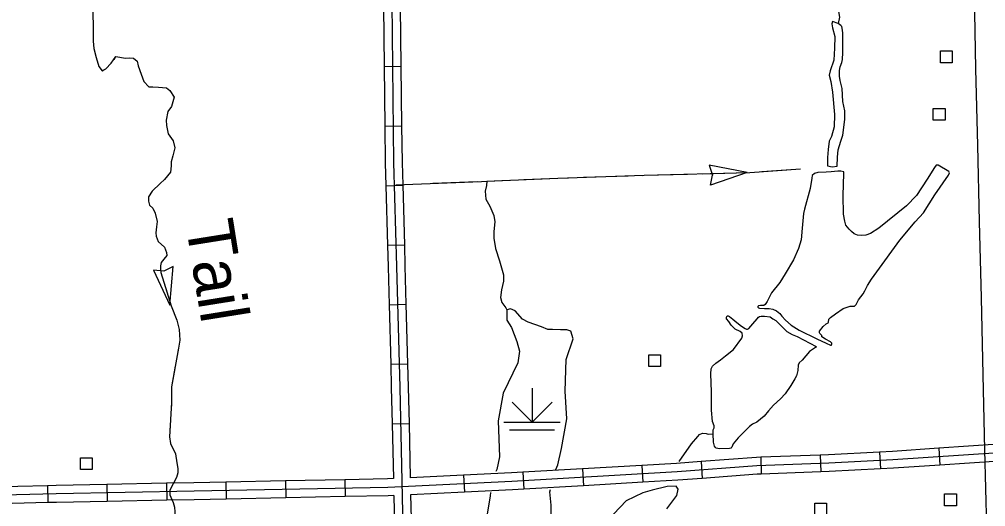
# Model space of a CAD drawing. Extents: x 1084508 to 1142749, y 1057638 to 1093403.
# Drawn here: x 1106590 to 1109281, y 1082416 to 1083772 of the extents above; entities that cross this region are included whole.
import ezdxf

# ---------------------------------------------------------------- set-up
doc = ezdxf.new("R2010")
doc.units = 0
for name, color, linetype in [('Level 10', 7, 'Continuous'), ('Level 32', 7, 'Continuous'), ('Level 35', 7, 'Continuous'), ('Level 43', 7, 'Continuous'), ('Level 44', 7, 'Continuous'), ('Level 47', 7, 'Continuous'), ('Level 56', 7, 'Continuous')]:
    doc.layers.add(name, color=color, linetype=linetype)

msp = doc.modelspace()

# ---------------------------------------------------------------- linework, layer by layer
at = {"layer": 'Level 10'}
msp.add_lwpolyline([(1109217.8, 1085327.2), (1109222.4, 1085115.2), (1109226.6, 1084906.4), (1109230, 1084691.2), (1109234.9, 1084482.4), (1109240.1, 1084267.5), (1109243.8, 1084054.2), (1109248.7, 1083844.6), (1109252.9, 1083634.1), (1109258.1, 1083420.9), (1109262.4, 1083209.7), (1109268.8, 1082997.4), (1109273.1, 1082783.1), (1109277.7, 1082574), (1109283.5, 1082358.9)], dxfattribs=at)
at = {"layer": 'Level 32'}
for p, q in [((1107605.5, 1083641), (1107652.6, 1083641.5)), ((1107607.4, 1083475.3), (1107654.5, 1083475.8)), ((1107610.4, 1083309.2), (1107657.5, 1083310.5)), ((1107615, 1083143.5), (1107662.1, 1083144.9)), ((1107619.6, 1082977.9), (1107666.6, 1082979.2)), ((1107624, 1082812.2), (1107671.1, 1082813.5)), ((1107628, 1082646.6), (1107675.1, 1082647.7)), ((1109150.2, 1082578.3), (1109153.4, 1082531.4)), ((1108654.4, 1082553.5), (1108656.1, 1082506.5)), ((1108820, 1082559.6), (1108821.7, 1082512.5)), ((1108985.2, 1082567.8), (1108987.6, 1082520.8)), ((1108323.3, 1082530.7), (1108326, 1082483.7)), ((1108488.2, 1082541.5), (1108491.8, 1082494.5)), ((1107827.1, 1082503.3), (1107829.3, 1082456.3)), ((1107992.3, 1082511.6), (1107995.1, 1082464.6)), ((1108157.8, 1082521.2), (1108160.5, 1082474.2)), ((1106667.9, 1082474.1), (1106669.1, 1082427)), ((1106833.7, 1082477.5), (1106834.7, 1082430.5)), ((1106999.4, 1082480.9), (1107000.4, 1082433.8)), ((1107165.1, 1082484.2), (1107166.1, 1082437.1)), ((1107330.8, 1082487.5), (1107331.8, 1082440.4)), ((1107496.5, 1082490.8), (1107497.5, 1082443.7))]:
    msp.add_line(p, q, dxfattribs=at)
for points in [[(1107601.5, 1085146.9), (1107603.3, 1084972.6), (1107614.1, 1084619.6), (1107615.9, 1084430.9), (1107624.9, 1083998.3), (1107632.1, 1083373.5), (1107640.3, 1083084.5), (1107649.3, 1082747.7), (1107660.1, 1082270)], [(1107603.6, 1083806.7), (1107605.5, 1083641)], [(1107650.7, 1083807.3), (1107652.6, 1083641.5)], [(1107605.5, 1083641), (1107607.4, 1083475.3)], [(1107652.6, 1083641.5), (1107654.5, 1083475.8)], [(1107607.4, 1083475.3), (1107608.6, 1083373), (1107610.4, 1083309.2)], [(1107654.5, 1083475.8), (1107655.7, 1083373.9), (1107657.5, 1083310.5)], [(1107610.4, 1083309.2), (1107615, 1083143.5)], [(1107657.5, 1083310.5), (1107662.1, 1083144.9)], [(1107615, 1083143.5), (1107616.7, 1083083.8), (1107619.6, 1082977.9)], [(1107662.1, 1083144.9), (1107663.8, 1083085.1), (1107666.6, 1082979.2)], [(1107619.6, 1082977.9), (1107624, 1082812.2)], [(1107666.6, 1082979.2), (1107671.1, 1082813.5)], [(1107624, 1082812.2), (1107625.7, 1082747.1), (1107628, 1082646.6)], [(1107671.1, 1082813.5), (1107672.8, 1082748.3), (1107675.1, 1082647.7)], [(1107628, 1082646.6), (1107631.5, 1082493.9)], [(1107675.1, 1082647.7), (1107678.5, 1082496.2)], [(1109150.2, 1082578.3), (1109021.3, 1082569.7), (1108985.2, 1082567.8)], [(1109315.6, 1082589.4), (1109150.2, 1082578.3)], [(1109317.2, 1082565.9), (1109022.7, 1082546.2), (1108844.3, 1082536.9), (1108643.6, 1082529.6), (1108421.8, 1082512.9), (1107961.6, 1082486.3), (1107616.3, 1082469.6), (1107076.7, 1082458.9), (1106692.8, 1082451.1), (1106360.3, 1082443)], [(1108654.4, 1082553.5), (1108642.3, 1082553.1), (1108488.2, 1082541.5)], [(1108820, 1082559.6), (1108654.4, 1082553.5)], [(1108985.2, 1082567.8), (1108843.3, 1082560.4), (1108820, 1082559.6)], [(1108323.3, 1082530.7), (1108157.8, 1082521.2)], [(1108488.2, 1082541.5), (1108420.3, 1082536.3), (1108323.3, 1082530.7)], [(1109153.4, 1082531.4), (1109024.1, 1082522.7), (1108987.6, 1082520.8)], [(1109318.7, 1082542.4), (1109153.4, 1082531.4)], [(1107827.1, 1082503.3), (1107678.5, 1082496.2)], [(1107992.3, 1082511.6), (1107960.3, 1082509.8), (1107827.1, 1082503.3)], [(1108157.8, 1082521.2), (1107992.3, 1082511.6)], [(1108656.1, 1082506.5), (1108644.9, 1082506.1), (1108491.8, 1082494.5)], [(1108821.7, 1082512.5), (1108656.1, 1082506.5)], [(1108987.6, 1082520.8), (1108845.4, 1082513.4), (1108821.7, 1082512.5)], [(1106667.9, 1082474.1), (1106502.3, 1082470)], [(1106833.7, 1082477.5), (1106692.2, 1082474.7), (1106667.9, 1082474.1)], [(1106999.4, 1082480.9), (1106833.7, 1082477.5)], [(1107165.1, 1082484.2), (1107076.2, 1082482.4), (1106999.4, 1082480.9)], [(1107330.8, 1082487.5), (1107165.1, 1082484.2)], [(1107496.5, 1082490.8), (1107330.8, 1082487.5)], [(1107631.5, 1082493.9), (1107615.5, 1082493.1), (1107496.5, 1082490.8)], [(1108160.5, 1082474.2), (1107995.1, 1082464.6)], [(1108326, 1082483.7), (1108160.5, 1082474.2)], [(1108491.8, 1082494.5), (1108423.4, 1082489.4), (1108326, 1082483.7)], [(1107497.5, 1082443.7), (1107331.8, 1082440.4)], [(1107632.6, 1082446.8), (1107617.1, 1082446.1), (1107497.5, 1082443.7)], [(1107632.6, 1082446.8), (1107635.5, 1082315.3)], [(1107829.3, 1082456.3), (1107679.6, 1082449.1)], [(1107679.6, 1082449.1), (1107682.6, 1082316.3)], [(1107995.1, 1082464.6), (1107962.8, 1082462.7), (1107829.3, 1082456.3)], [(1106669.1, 1082427), (1106503.4, 1082423)], [(1106834.7, 1082430.5), (1106693.3, 1082427.6), (1106669.1, 1082427)], [(1107000.4, 1082433.8), (1106834.7, 1082430.5)], [(1107166.1, 1082437.1), (1107077.1, 1082435.3), (1107000.4, 1082433.8)], [(1107331.8, 1082440.4), (1107166.1, 1082437.1)]]:
    msp.add_lwpolyline(points, dxfattribs=at)
at = {"layer": 'Level 35'}
for points in [[(1108870.3, 1083760.9), (1108854, 1083766.3), (1108852.4, 1083760.1), (1108854.8, 1083748.4), (1108861, 1083724.3), (1108860.2, 1083691.6), (1108857.9, 1083658.9), (1108847.8, 1083629.3), (1108845.4, 1083616.8), (1108849.3, 1083598.9), (1108854.8, 1083569.3), (1108860.2, 1083507.8), (1108858.6, 1083473.3), (1108851.6, 1083446.1), (1108845.4, 1083432.9), (1108842.3, 1083410.3), (1108840.4, 1083388)], [(1108840.4, 1083388), (1108840.1, 1083364.7), (1108853.4, 1083361.3), (1108867.2, 1083363.2), (1108868.3, 1083388.5), (1108869.7, 1083409.3), (1108877.1, 1083433.1), (1108883.4, 1083449.8), (1108885.3, 1083463.4), (1108888.4, 1083494.2), (1108888.4, 1083517.3), (1108883.3, 1083543.3), (1108881.4, 1083579.9), (1108876, 1083601.7), (1108873.6, 1083614.2), (1108873.6, 1083622.4), (1108873.6, 1083630.2), (1108875.6, 1083640.3), (1108880.6, 1083652.3), (1108881.8, 1083660.9), (1108883, 1083679.6), (1108883, 1083733.8), (1108881.8, 1083742.4), (1108880.6, 1083752.5), (1108877.1, 1083755.6), (1108870.3, 1083760.9)], [(1106859, 1083668.4), (1106885.4, 1083664.4), (1106896.4, 1083665.3), (1106907.3, 1083664.4), (1106917.9, 1083656.1), (1106920.5, 1083643.3), (1106929.3, 1083619.6), (1106936.3, 1083599.4), (1106950, 1083584.8), (1106961.8, 1083584), (1106977.6, 1083583.5), (1106999.6, 1083581.8), (1107008.8, 1083574.3), (1107021.1, 1083555.4), (1107013.7, 1083529.5), (1107003.6, 1083515.4), (1106998.3, 1083492.1), (1107000.1, 1083476.7), (1107004.4, 1083453.8), (1107018.5, 1083434.5), (1107023.3, 1083414.3), (1107017.6, 1083392.3), (1107012.4, 1083375.2), (1107012.4, 1083364.6), (1107011, 1083346.9), (1106994.3, 1083326.7), (1106982, 1083315.7), (1106959.6, 1083294.2), (1106949.1, 1083278.4), (1106949.1, 1083266.5), (1106952.2, 1083255.5), (1106961.8, 1083246.7), (1106968.4, 1083233.1), (1106973.7, 1083209.8), (1106971.5, 1083194.4), (1106970.2, 1083178.1), (1106971, 1083168.9), (1106976.3, 1083153.5), (1106993.9, 1083137.7), (1107000, 1083123.2), (1107000.9, 1083114.7), (1106992.6, 1083105), (1106984.7, 1083095.8), (1106983.3, 1083086.1), (1106983.3, 1083078.7), (1106983.9, 1083067.3)], [(1108849.2, 1082942.3), (1108863, 1082952.4), (1108884, 1082967.6), (1108903.1, 1082973.8), (1108915.5, 1082974.2), (1108920.2, 1082978.9), (1108927.2, 1082991.7), (1108940, 1083008.5), (1108944.3, 1083016.2), (1108951.7, 1083031), (1108963, 1083048.9), (1108978.2, 1083069.6), (1109041.6, 1083157.2), (1109084.4, 1083208.2), (1109108.1, 1083233.9), (1109139.6, 1083283.7), (1109177, 1083338.5), (1109180.1, 1083345.5), (1109178.6, 1083349), (1109148.6, 1083366.5), (1109143.5, 1083366.5), (1109138.5, 1083360.3), (1109117.9, 1083327.2), (1109087.9, 1083282), (1109060.7, 1083253.6), (1108983.6, 1083190.6), (1108960.3, 1083176.2), (1108947, 1083171.5), (1108934.2, 1083170.7), (1108923.7, 1083171.5), (1108915.1, 1083175), (1108907.4, 1083181.6), (1108900.4, 1083188.6), (1108891.4, 1083199.1), (1108889.1, 1083210.4), (1108884.8, 1083229.9), (1108883.6, 1083282), (1108886.3, 1083342.8), (1108886, 1083347.4), (1108877.4, 1083349.4), (1108869.2, 1083349.4), (1108850.9, 1083348.2), (1108836.5, 1083347.1), (1108813.6, 1083345.9), (1108803.9, 1083343.2), (1108797.6, 1083337.3), (1108796.5, 1083330.3), (1108791.8, 1083301.5), (1108776.2, 1083243.9), (1108773.5, 1083231.4), (1108770, 1083191), (1108766.9, 1083159), (1108759.5, 1083134.5), (1108745.5, 1083103), (1108722.9, 1083063.9)], [(1107891.6, 1083322.2), (1107890.6, 1083309.4), (1107887.5, 1083293.9), (1107889, 1083271.3), (1107899.8, 1083252.3), (1107911.1, 1083226.6), (1107914.2, 1083208.6), (1107911.1, 1083181.3), (1107911.6, 1083163.2), (1107915.7, 1083134.4), (1107927, 1083100), (1107937.8, 1083061.4), (1107937.8, 1083043.4), (1107932.7, 1083019.2), (1107929.6, 1082998.1), (1107933.2, 1082983.7), (1107945, 1082969.3), (1107947.5, 1082963.3)], [(1108722.9, 1083063.9), (1108707.3, 1083039.5), (1108684.6, 1083011.1), (1108672.1, 1082986.6), (1108666.7, 1082978.4), (1108662.8, 1082976.1), (1108653.5, 1082975.3), (1108648, 1082974.5), (1108646.8, 1082973), (1108646.8, 1082971), (1108648, 1082969.5), (1108651.1, 1082968.3), (1108664.7, 1082967.5), (1108678.4, 1082967.5), (1108688.1, 1082965.6), (1108698.6, 1082960.5), (1108707.5, 1082953.5), (1108713.4, 1082946.5), (1108723.5, 1082934.9)], [(1108524.9, 1082640.4), (1108520.6, 1082652.7), (1108517.7, 1082684.1), (1108517.5, 1082735.5), (1108515.7, 1082785.7), (1108516.2, 1082799.6), (1108520.6, 1082806.5), (1108529.3, 1082815), (1108542.7, 1082824.3), (1108556, 1082835.8), (1108578.6, 1082853.3), (1108602.3, 1082885), (1108604.1, 1082891.1), (1108602.6, 1082899.1), (1108597.4, 1082903.7), (1108583.5, 1082909.7), (1108572.2, 1082920.8), (1108565.5, 1082931.6), (1108559.4, 1082939), (1108559.4, 1082943.7), (1108561.2, 1082947), (1108564, 1082947), (1108567.3, 1082945.2), (1108576.6, 1082938), (1108587.9, 1082928.2), (1108600.5, 1082918.2), (1108611.3, 1082911.3), (1108614.6, 1082910.2), (1108617.7, 1082910.2), (1108621.8, 1082912), (1108627.2, 1082918.2), (1108632.6, 1082924.9), (1108644.7, 1082938.8), (1108648.3, 1082943.4), (1108651.1, 1082944.7), (1108656, 1082946.2), (1108664.8, 1082946.2), (1108680.7, 1082943.9), (1108688.1, 1082939), (1108696.1, 1082934.4), (1108712.8, 1082917.2), (1108727.2, 1082903.3), (1108742.1, 1082895), (1108756.3, 1082889.8), (1108808.4, 1082861.3), (1108807.1, 1082858.5), (1108801.5, 1082855.6), (1108790.4, 1082847.6), (1108779.9, 1082835.3), (1108769.6, 1082823.5), (1108761.1, 1082815.8), (1108758.6, 1082809.3), (1108757.5, 1082795.2), (1108753.7, 1082780.3), (1108749.8, 1082771.5), (1108738.5, 1082753.5), (1108722.8, 1082729.9), (1108709.7, 1082716), (1108690.2, 1082698.5), (1108676.1, 1082682.6), (1108664, 1082667.4), (1108643.2, 1082651.4), (1108631.8, 1082645), (1108623.1, 1082639.4), (1108615.7, 1082631.6), (1108600, 1082615.7), (1108592, 1082607.7), (1108578.1, 1082590.5), (1108574, 1082581.7), (1108572.2, 1082579.9), (1108571.7, 1082578.7), (1108567.6, 1082577.6), (1108540.1, 1082577.1), (1108530.6, 1082578.4), (1108527.5, 1082581), (1108525.7, 1082584.3), (1108523.1, 1082594.9), (1108521.8, 1082618.3), (1108522.1, 1082630), (1108524.4, 1082635.1), (1108524.9, 1082640.4)], [(1108723.5, 1082934.9), (1108739.1, 1082921.3), (1108761.2, 1082906.9), (1108811, 1082882.7), (1108836.3, 1082871), (1108849.2, 1082865.6), (1108851.1, 1082865.6), (1108851.9, 1082866.4), (1108852.3, 1082868.7), (1108852.3, 1082871), (1108848.8, 1082874.5), (1108834.8, 1082881.9), (1108825, 1082889), (1108824.3, 1082892.1), (1108822.3, 1082894.8), (1108818.8, 1082897.5), (1108818, 1082899.5), (1108818.4, 1082904.1), (1108828.5, 1082917), (1108836.3, 1082924.8), (1108842.2, 1082927.9), (1108843.3, 1082929.8), (1108844.5, 1082937.6), (1108849.2, 1082942.3)], [(1108427.5, 1082541.8), (1108462, 1082591), (1108479.7, 1082611.3), (1108483.8, 1082617), (1108492.5, 1082620.8), (1108502.3, 1082619.5), (1108508.5, 1082618), (1108521.8, 1082618.3)]]:
    msp.add_lwpolyline(points, dxfattribs=at)
at = {"layer": 'Level 43'}
for p, q in [((1108616.3, 1083345.7), (1108510.5, 1083366)), ((1108510.5, 1083366), (1108519.9, 1083338.9)), ((1108616.3, 1083345.7), (1108514.5, 1083310.4)), ((1108514.5, 1083310.4), (1108519.9, 1083338.5)), ((1106991.8, 1083071.7), (1106963.2, 1083074)), ((1106963.2, 1083074), (1107009.3, 1082976.6)), ((1107018.1, 1083084), (1106992.2, 1083071.7)), ((1107009.3, 1082976.6), (1107018.1, 1083084))]:
    msp.add_line(p, q, dxfattribs=at)
for points in [[(1108848.2, 1085865.1), (1108854.4, 1085762.3), (1108857.5, 1085642.4), (1108872.3, 1085194.7), (1108873.8, 1085105.2), (1108883.9, 1084848.3), (1108882.6, 1084834.1), (1108883, 1084829), (1108887.6, 1084812.3), (1108889.2, 1084796.7), (1108892.3, 1084754.3), (1108892.7, 1084638.3), (1108882.2, 1084627.4), (1108876, 1084447.8), (1108866.4, 1084161.2), (1108861, 1084003.2), (1108861.8, 1083943.1), (1108860.2, 1083922), (1108858.6, 1083894), (1108861, 1083855.9), (1108874.2, 1083778), (1108870.3, 1083760.9)], [(1106790.9, 1084012.1), (1106794.9, 1083830.6), (1106795.7, 1083711.9), (1106797.1, 1083691.2), (1106804.1, 1083666.2), (1106811.1, 1083640.7), (1106820.8, 1083628.8), (1106830.5, 1083634.5), (1106845.8, 1083650.3), (1106859, 1083668.4)], [(1106795.5, 1083742.9), (1106795.7, 1083711.9), (1106797.1, 1083691.2), (1106804.1, 1083666.2), (1106811.1, 1083640.7), (1106820.8, 1083628.8), (1106824.9, 1083631.3)], [(1106853.5, 1083660.8), (1106859, 1083668.4)], [(1107891.6, 1083322.2), (1108089.8, 1083330.3), (1108330.2, 1083338.1), (1108624.1, 1083345.9), (1108765.3, 1083356.2)], [(1107995.1, 1083326.5), (1108089.8, 1083330.3), (1108119.3, 1083331.3)], [(1108160.7, 1083332.6), (1108284.9, 1083336.7)], [(1108326.3, 1083338), (1108330.2, 1083338.1), (1108450.6, 1083341.3)], [(1108492, 1083342.4), (1108616.3, 1083345.7)], [(1108657.6, 1083348.3), (1108765.3, 1083356.2)], [(1107638.1, 1083312), (1107876.7, 1083321.2), (1107891.6, 1083322.2)], [(1107741.7, 1083316), (1107865.9, 1083320.8)], [(1107891.6, 1083322.2), (1107953.7, 1083324.8)], [(1106983.9, 1083067.3), (1107012.9, 1082975), (1107028.1, 1082935.3), (1107035, 1082908.6), (1107036.5, 1082879.6), (1107032.7, 1082857.4), (1107013.6, 1082749.1), (1107013.6, 1082705.6), (1107008.3, 1082610.2), (1107010.6, 1082591.8), (1107025.1, 1082562.8), (1107028.1, 1082537.6), (1107031.2, 1082522.3), (1107031.2, 1082510.1), (1107027.4, 1082497.1), (1107009, 1082461.3), (1107009, 1082448.3), (1107018.2, 1082427.7), (1107022, 1082414)], [(1106983.9, 1083067.3), (1107002.5, 1083008)], [(1107024.5, 1082944.6), (1107028.1, 1082935.3), (1107035, 1082908.6), (1107036.5, 1082879.6), (1107032.7, 1082857.4), (1107031, 1082848.1)], [(1107023.9, 1082807.2), (1107013.6, 1082749.1), (1107013.6, 1082705.6), (1107012.4, 1082683.9)], [(1107010.1, 1082642.5), (1107008.3, 1082610.2), (1107010.6, 1082591.8), (1107025.1, 1082562.8), (1107028.1, 1082537.6), (1107031.2, 1082522.3), (1107031.2, 1082522.3)], [(1107020.1, 1082421), (1107022, 1082414), (1107023.5, 1082388), (1107021.7, 1082364.1)]]:
    msp.add_lwpolyline(points, dxfattribs=at)
at = {"layer": 'Level 44'}
for p, q in [((1108017.8, 1082745.3), (1108017.8, 1082651.2)), ((1108017.8, 1082651.2), (1107962.3, 1082706.7)), ((1108017.8, 1082651.2), (1108073.3, 1082706.7)), ((1107939.3, 1082651.2), (1108096.3, 1082651.2)), ((1107955, 1082629.8), (1108080.6, 1082629.8))]:
    msp.add_line(p, q, dxfattribs=at)
at = {"layer": 'Level 47'}
for points in [[(1108084.1, 1082519.3), (1108089.8, 1082532.4), (1108100, 1082577.6), (1108114.1, 1082659.9), (1108109.6, 1082737.1), (1108112.8, 1082825.2), (1108132.4, 1082883.2), (1108125.6, 1082904.5), (1108114.5, 1082907.9), (1108096.6, 1082907.9), (1108074.4, 1082908.8), (1108061.7, 1082908.8), (1108043.8, 1082916.4), (1108007.1, 1082929.2), (1107990.9, 1082937.7), (1107970.5, 1082960.8), (1107957.9, 1082966.7), (1107947.5, 1082963.3), (1107947.5, 1082935.2), (1107960.2, 1082914.7), (1107975.6, 1082875.7), (1107982.4, 1082848.5), (1107977.8, 1082816.6), (1107936.9, 1082731.5), (1107923.3, 1082654.3), (1107927, 1082554.9), (1107919.3, 1082519.1), (1107917.1, 1082513.3)], [(1108421.3, 1082446.7), (1108424.7, 1082464.8), (1108419, 1082472.8), (1108394, 1082471.6), (1108352, 1082461.4), (1108325.9, 1082454.6)], [(1107901.9, 1082455.4), (1107900.6, 1082445.8), (1107892.9, 1082394.7), (1107887, 1082352), (1107885.3, 1082280.4), (1107900.6, 1082124.4), (1107892.1, 1082074.9), (1107869.9, 1082036.6), (1107853.7, 1082020.4), (1107845.2, 1081999.9), (1107845.2, 1081986.3), (1107846.9, 1081955.6), (1107864, 1081932.6), (1107895.5, 1081901), (1107943.2, 1081833.7), (1107959.4, 1081784.2)], [(1108325.9, 1082454.6), (1108279.3, 1082431.9), (1108209.9, 1082358.5), (1108132.4, 1082280.9), (1108099.2, 1082247.7), (1108088.1, 1082248.5), (1108074.4, 1082258.8), (1108073.6, 1082292), (1108071, 1082367), (1108071, 1082419.9), (1108067.6, 1082457.4), (1108068.6, 1082463.3)], [(1108393.1, 1082409.7), (1108421.3, 1082446.7)]]:
    msp.add_lwpolyline(points, dxfattribs=at)
at = {"layer": 'Level 56'}
for points in [[(1109155, 1083651.6), (1109155, 1083684.2), (1109187.8, 1083684.2), (1109187.8, 1083651.6)], [(1109135, 1083491.5), (1109135, 1083524.2), (1109167.8, 1083524.2), (1109167.8, 1083491.5)], [(1108342.5, 1082805.8), (1108342.5, 1082838.5), (1108375.3, 1082838.5), (1108375.3, 1082805.8)], [(1106760.2, 1082519.2), (1106760.2, 1082551.9), (1106793, 1082551.9), (1106793, 1082519.2)], [(1109166.5, 1082418.5), (1109166.5, 1082451.2), (1109199.3, 1082451.2), (1109199.3, 1082418.5)], [(1108805, 1082392.7), (1108805, 1082425.4), (1108837.8, 1082425.4), (1108837.8, 1082392.7)]]:
    msp.add_lwpolyline(points, close=True, dxfattribs=at)

# ---------------------------------------------------------------- texts
at = {"layer": 'Level 35'}
msp.add_text('Tail', height=132.58, rotation=279.0642, dxfattribs=at).set_placement((1107052.7, 1083203.7))

doc.saveas('drawing.dxf')
